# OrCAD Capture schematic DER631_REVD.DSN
size Custom
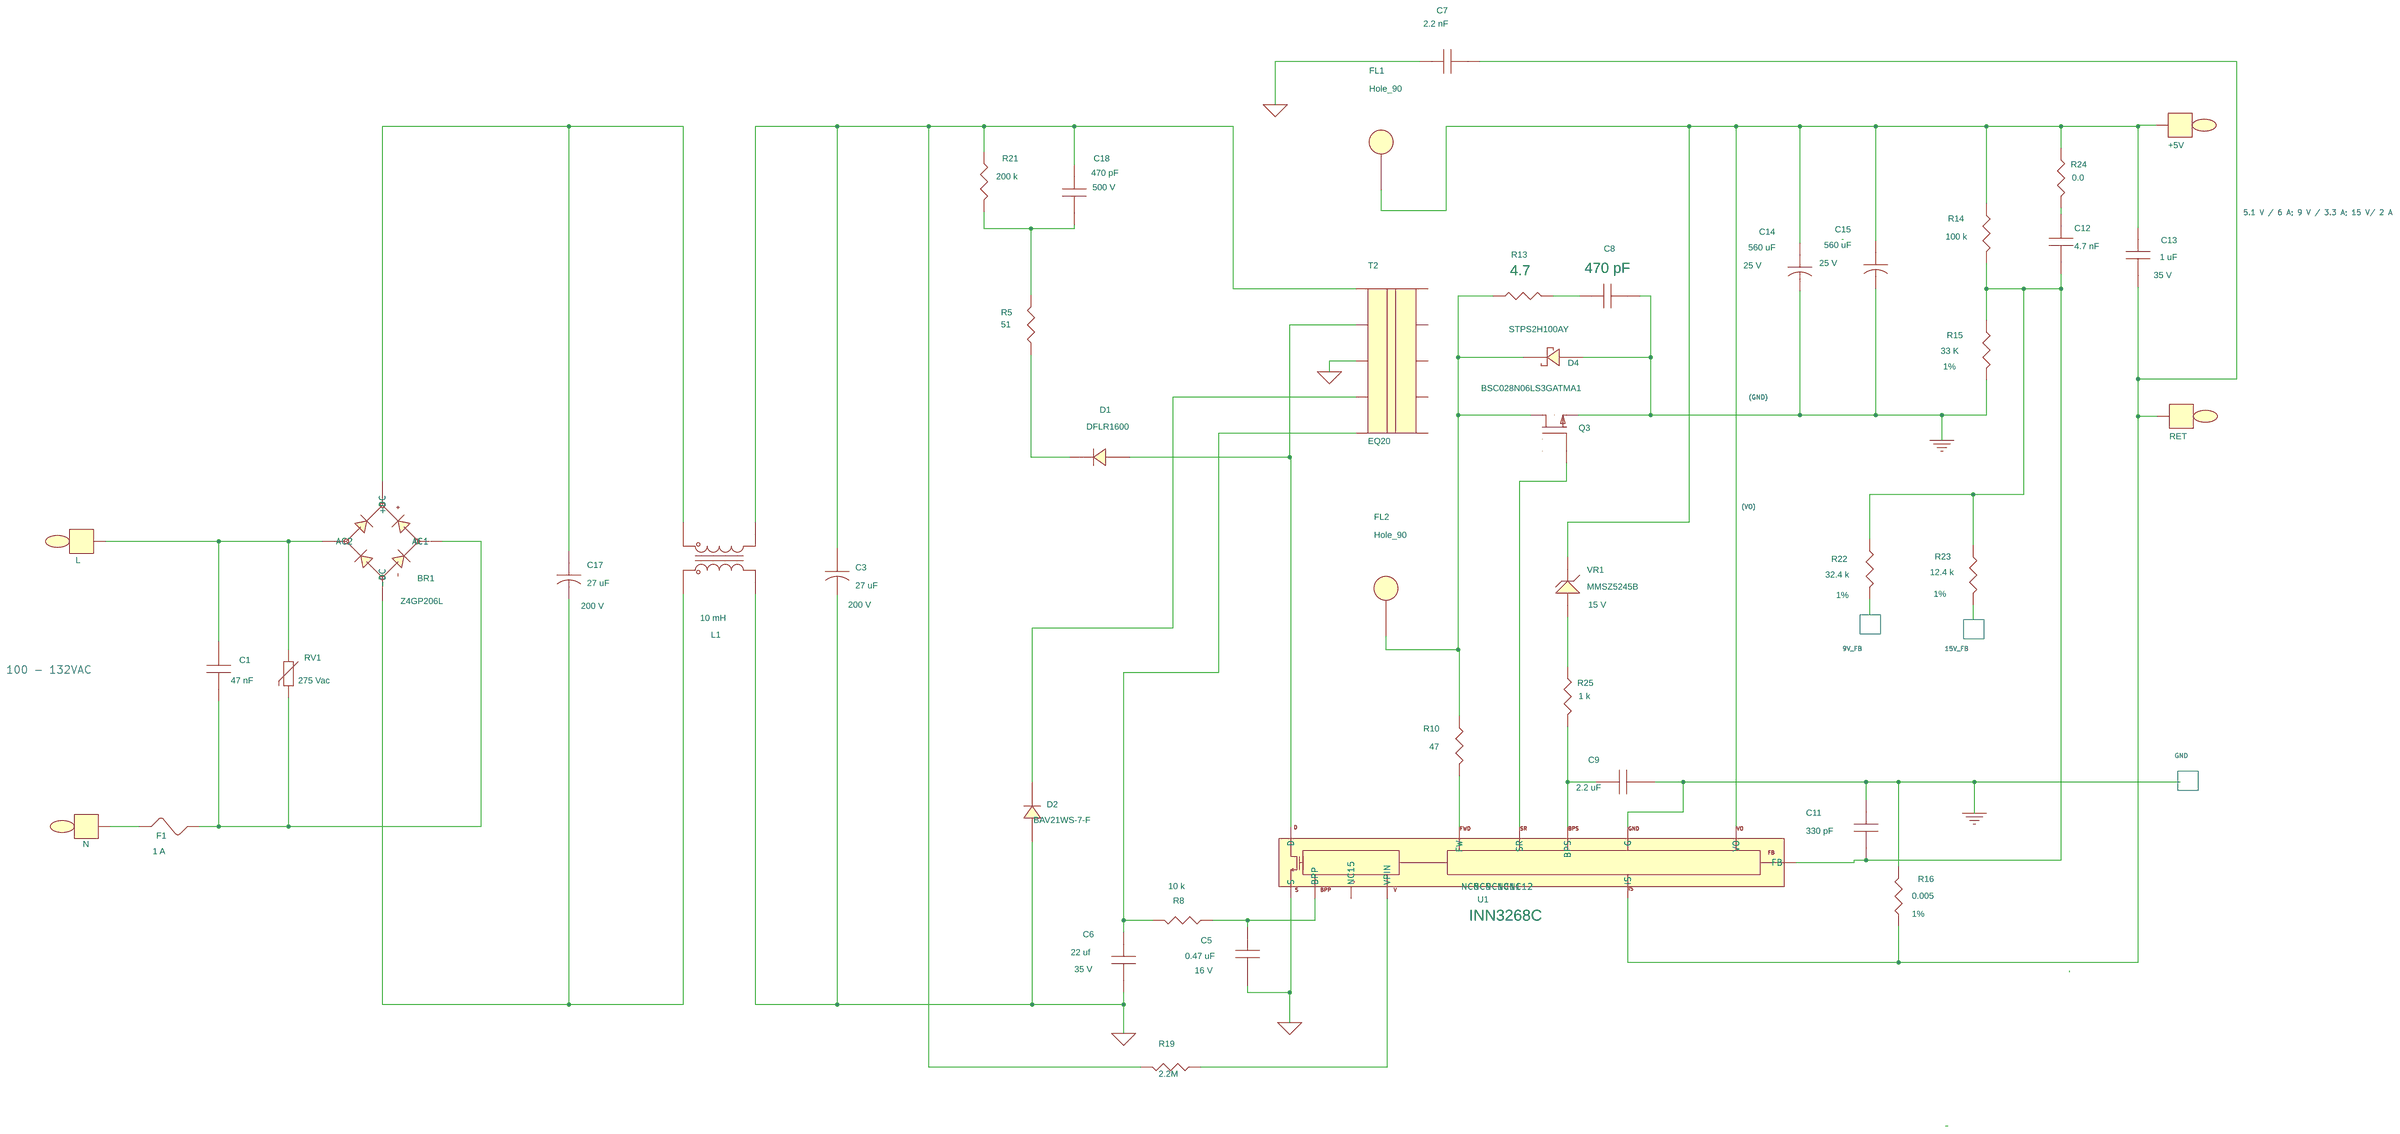
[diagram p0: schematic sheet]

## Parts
BR1  Z4GP206L  [pi_sm_d_z4]
C1  47 nF  [PI_NP395X200LS300D040]
C3  27 uF  [pipolcapcyld400ls200040]
C5  0.47 uF  [pismc0603]
C6  22 uf  [pismc1206]
C7  2.2 nF  [pinpcaprad374x275ls394d030]
C8  470 pF  [pismc0603]
C9  2.2 uF  [pismc0603]
C11  330 pF  [pismc0603]
C12  4.7 nF  [pismc0603]
C13  1 uF  [pismc0603]
C14  560 uF  [pipolcapcyld400ls200040]
C15  560 uF  [pipolcapcyld400ls200040]
C17  27 uF  [pipolcapcyld400ls200040]
C18  470 pF  [pismc1206]
D1  DFLR1600  [pismddflr120012]
D2  BAV21WS-7-F  [pismsod323]
D4  STPS2H100AY  [pismdsma]
F1  1 A  [pi_rst_microfuse]
FL1  Hole_90  [pi_hole_70mil]
FL2  Hole_90  [pi_hole_70mil]
L1  10 mH  [pi_ind_4p_590x295ls394x177d060]
Q3  BSC028N06LS3GATMA1  [pi_sm_pg-tdson-8]
R5  51  [pismr1206]
R8  10 k  [pismr0603]
R10  47  [pismr0603]
R13  4.7  [pismr0603]
R14  100 k  [pismr0603]
R15  33 K  [pismr0603]
R16  0.005  [pismr0805]
R19  2.2M  [pismr1206]
R21  200 k  [pismr1206]
R22  32.4 k  [pismr0603]
R23  12.4 k  [pismr0603]
R24  0.0  [pismr0603]
R25  1 k  [pismr0603]
RV1  275 Vac  [pidisc350x160ls210x140040]
T2  EQ20  [Pi_Bobbin_EQ20_10P_H]
TP1  L  [pitpkeystone100x100]
TP2  N  [pitpkeystone100x100]
TP10  RET  [pitpkeystone100x100]
TP11  +5V  [pitpkeystone100x100]
U1  INN3268C  [pi_ic_insop_24d]
VR1  MMSZ5245B  [pi_sm_sod-123_12]

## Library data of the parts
BR1 = DISCRETE_BRIDGE_+~~-: Part Number: 15-01115-00
C1 = CAP_NP: COMPGROUP: 1; Disp_Voltage: 310 VAC; Part Number: 20-01115-00; Voltage: 310 VAC
C3 C17 = CAP_POL: ALT_SYMBOLS: pipolcapclyd400x675ls200040h; Disp_Voltage: 200 V; FPLIST: pipolcapcyld400ls200040,pipolcapclyd400x675ls200040h; Part Number: 20-00610-00; Voltage: 200 V
C5 = CAP_NP: Disp_Voltage: 16 V; Part Number: 20-08990-00; Voltage: 16 V
C6 = CAP_NP: Disp_Voltage: 35 V; Part Number: 20-01138-00; Voltage: 35 V
C7 = CAP_NP: COMPGROUP: 3; Disp_Voltage: 400 VAC; PCB Editor PCBFP: pinpycaprad540x290ls400040; Part Number: 20-08896-00; Voltage: 400 VAC
C8 = CAP_NP: Disp_Voltage: 200 V; Part Number: 20-00529-00; Voltage: 200 V
C9 = CAP_NP: Disp_Voltage: 10 V; Part Number: 20-08740-00; Voltage: 10V
C11 = CAP_NP: Disp_Voltage: 50 V; Part Number: 20-08676-00; Voltage: 50 V
C12 = CAP_NP: Disp_Voltage: 50 V; Part Number: 20-08578-00; Voltage: 50 V
C13 = CAP_NP: Disp_Voltage: 35 V; Part Number: 20-01134-00; Voltage: 35 V
C14 C15 = CAP_POL: COMPGROUP: 3; Disp_Voltage: 25 V; Part Number: 20-09046-00; Voltage: 25 V
C18 = CAP_NP: Disp_Voltage: 500 V; Part Number: 20-08965-00; Voltage: 500 V
D1 = DIODE: Disp_Voltage: 600 V; Part Number: 15-00826-00
D2 = DIODE: COMPGROUP: 1; Part Number: 15-00385-00
D4 = DIODE_SCHOTTKY: Disp_Voltage: 100 V; Part Number: 15-00985-00
F1 = FUSE: ALT_SYMBOLS: pirstmicrofusehoz; FPLIST: pi_rst_microfuse,pirstmicrofusehoz; Part Number: 40-00053-00
FL1 FL2 = FlyingLead: Part Number: 35-00282-00
L1 = INDUCTOR_4P_revD: Part Number: 30-00410-00
Q3 = FET_N_TSDSON-8: Part Number: 50-00245-00
R5 = R: Part Number: 05-01321-00
R8 = R: Part Number: 05-01712-00
R10 = R: Part Number: 05-01656-00
R13 = R: Part Number: 05-01632-00
R14 = R: Disp_Tol: 1%; Part Number: 05-01174-00
R15 = R: Disp_Tol: 1%; Part Number: 05-06465-00
R16 = R: Disp_Tol: 1%; Part Number: 05-06348-00
R19 = R: Part Number: 05-01429-00
R21 = R: Part Number: 05-01407-00
R22 = R: Disp_Tol: 1%; Part Number: 05-03233-00
R23 = R: Disp_Tol: 1%; Part Number: 05-03191-00
R24 = R: Part Number: 05-03158-00
R25 = R: Part Number: 05-01688-00
RV1 = VARISTOR: ALT_SYMBOLS: pi_disc_354x220_ls220x10_040_h; FPLIST: pidisc350x160ls210x140040,pi_disc_354x220_ls220x10_040_h; Part Number: 85-00015-00
T2 = BEQ20_10P: Part Number: 25-01121-00
TP1 TP10 TP11 = TESTPOINT: Part Number: 35-00079-00
TP2 = TESTPOINT: Part Number: 35-00081-00
U1 = DEV_InSOP_0: Part Number: 10-00915-00
VR1 = DIODE_ZENER: Disp_Voltage: 15 V; Part Number: 15-01032-00

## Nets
GND_POWER: C8.2 C9.2 C11.1 C14.2 C15.2 D4.2 Q3.1(S1) R15.2 R16.1 U1.2(G)
GND_SIGNAL: C3.2 C5.2 C6.2 C7.1 D2.2 L1.2 T2.3 U1.16(S)
D6: Q3.6(D6)
D7: Q3.7(D7)
D8: Q3.8(D8)
NC8: U1.8(NC8)
NC9: U1.9(NC9)
NC10: U1.10(NC10)
NC11: U1.11(NC11)
NC12: U1.12(NC12)
NC15: U1.15(NC15)
S2: Q3.2(S2)
S3: Q3.3(S3)
N11018979: C13.1 C14.1 C15.1 FL1.1 R14.1 R24.1 TP11.1 U1.6(VO) VR1.1
N11018987: C7.2 C13.2 R16.2 TP10.1 U1.1(IS)
N11019023: R10.2 U1.7(FW)
N11019027: D4.1 FL2.1 Q3.5(D5) R10.1 R13.2
N11019129: Q3.4(G) U1.5(SR)
N11019153: D1.1 R5.2
N11019263: BR1.4(-DC) C17.2 L1.1
N11019293: C5.1 R8.2 U1.14(BPP)
N11019397: BR1.3(AC2) C1.1 RV1.1 TP1.1
N11019401: C8.1 R13.1
N11019569: C6.1 R8.1 T2.5
N11019593: R19.2 U1.13(VPIN)
N11019613: C3.1 C18.1 L1.3 R19.1 R21.1 T2.1
N11019673: BR1.2(AC1) C1.2 F1.2 RV1.2
N11019681: BR1.1(+DC) C17.1 L1.4
N11019743: C11.2 C12.2 R14.2 R15.1 R22.1 R23.1 U1.3(FB)
N11020702: C18.2 R5.1 R21.2
N11020753: D1.2 T2.2 U1.24(D)
N11026403: F1.1 TP2.1
N11053934: D2.1 T2.4
N11111738: C12.1 R24.2
N11113310: C9.1 R25.2 U1.4(BPS)
N11114484: R25.1 VR1.2

Not connected (* = marked no-connect by the designer): R22 2; R23 2; T2 6 7 8 9 10

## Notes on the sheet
- 5.1 V / 6 A; 9 V / 3.3 A; 15 V/ 2 A
- (GND)
- (VO)
- 9V_FB
- 15V_FB
- 100 - 132VAC
- GND
